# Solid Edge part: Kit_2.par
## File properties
Author: bmolnar
Last saved by: bmolnar
Revision: 79
Sűrűség: 0,000 kg/m^3
Pontosság: 0,990
Username: bmolnar
Dokumentum tartalom típus: 0
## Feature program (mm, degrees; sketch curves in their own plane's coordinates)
base feature "unnamed BaseFeature 1"
thread "unnamed Thread 1"
thread "unnamed Thread 2"
thread "unnamed Thread 3"
thread "unnamed Thread 4"
sketch for "Furat_1" plane through (56.65, 0, -134.65) normal (-1, 0, 0) x-axis (0, 1, 0)
  hole centre (0, -47.65) bore radius 4.283
hole "Furat_1" nominal diameter 9.728 finite  ThreadDepth = 12 mm
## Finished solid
Body 1: solid body, 320 faces, 792 edges, 492 vertices.
  Faces by surface: plane 145, cylinder 82, swept 56, cone 25, torus 11, spline 1
  Edges by curve: line 446, circle 180, spline 136, ellipse 28, curve on surface 2
Bounding box of the edges (mm; curved faces can reach further): 113.300 x 113.300 x 19.500, from (-56.65, -56.65, -97.5) to (56.65, 56.65, -78).
Cylindrical faces by radius (mm): R0.2 x48, R0.2006 x2, R0.2007 x2, R4.188 x4, R4.283 x1, R6.35 x4, R6.55 x4, R6.75 x4, R12.8 x1, R13.45 x1, R14 x1, R14.9 x1, R15 x1, R51.85 x8
Conical faces (half-angle, radius in mm at the cone's reference point): 0.5 deg R12.25 x4, 0.5 deg R35 x2, 3 deg R14.95 x1, 7 deg R14.2695 x1, 14 deg R12.65 x1, 14 deg R13.057 x1, 17 deg R12.65 x1, 23 deg R13.4211 x1, 42.5 deg R12.637 x1, 45 deg R4.588 x8, 45 deg R13.6 x1, 84 deg R13.012 x1, 85 deg R14.6625 x1, 87 deg R12.7157 x1
Toroidal faces (ring radius, tube radius in mm): R6.05 r0.3 x2, R6.15 r0.2 x6, R13.4008 r0.225 x1, R13.8914 r0.325 x1, R14.7 r0.2 x1
Planar faces by outward normal: +x 17, +y 14, +z 2, -x 14, -y 16, -z 19, oblique 63
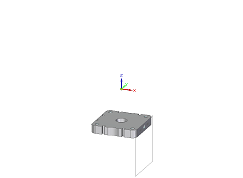
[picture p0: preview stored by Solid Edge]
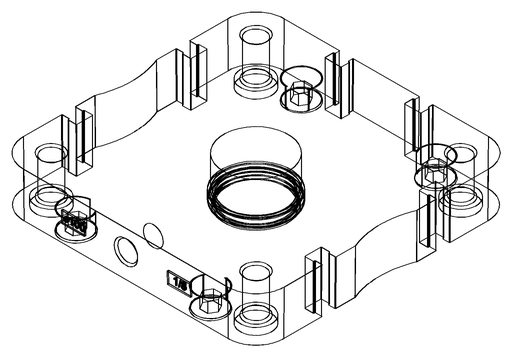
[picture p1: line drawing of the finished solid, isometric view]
